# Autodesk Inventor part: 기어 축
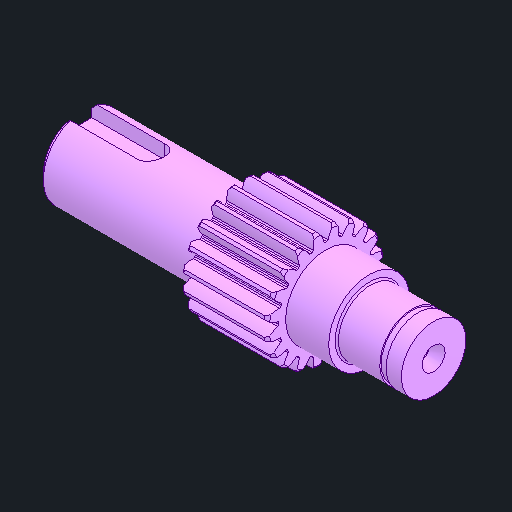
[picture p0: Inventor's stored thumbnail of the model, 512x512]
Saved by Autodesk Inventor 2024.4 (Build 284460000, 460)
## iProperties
Created: 2026-03
Part Number: 기어 축
Material: 강철, 합금
Document SubType Name: Modeling
Designer: user
Density: 7.73 g/cm^3
Appearance: 기본값
Author: jhkim
Sending System: Autodesk Inventor 2026
Preprocessor: ST-DEVELOPER v20.1
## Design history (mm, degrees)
feature "솔리드1"
node "솔리드2"
